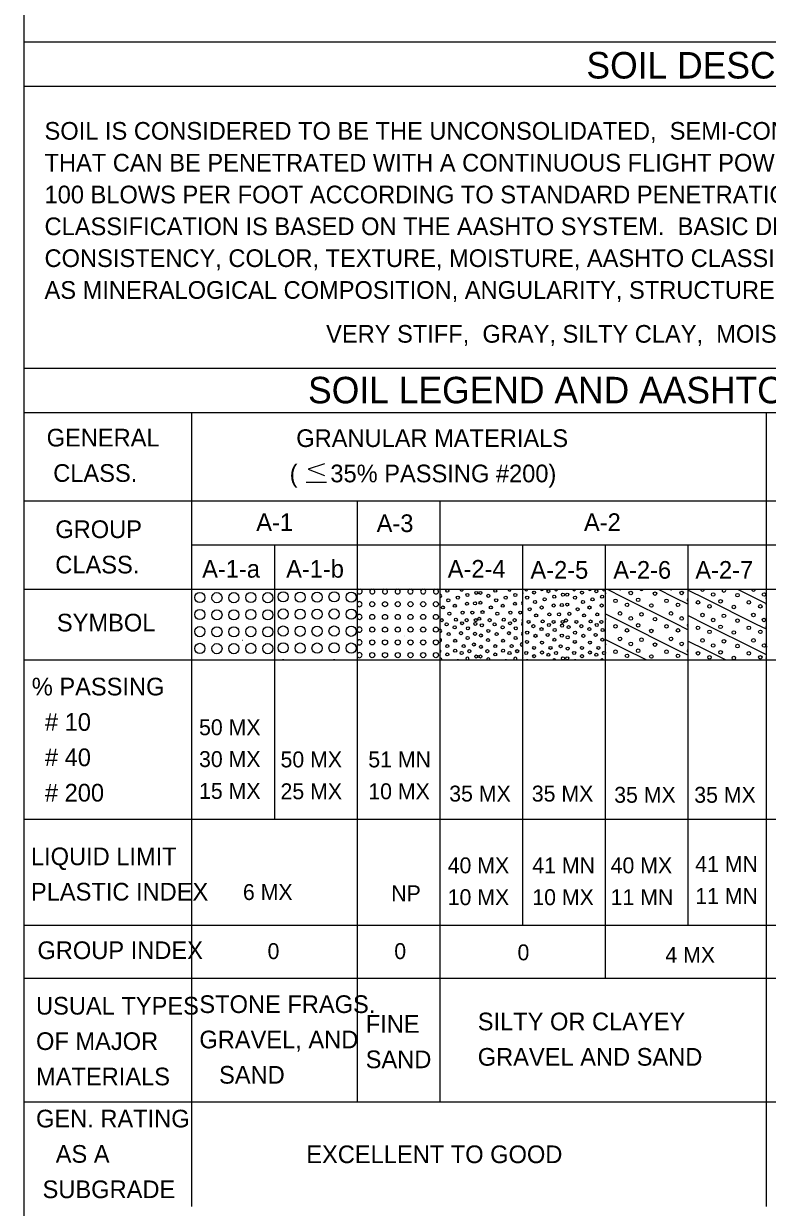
# Model space of a CAD drawing. Extents: x 278710 to 279187, y 171464 to 171625.
# Drawn here: x 279005.33 to 279023.58, y 171537.43 to 171566.47 of the extents above; entities that cross this region are included whole.
import ezdxf

# ---------------------------------------------------------------- set-up
doc = ezdxf.new("R2010")
doc.units = 0
doc.layers.add('Geotech Sheets and Borders Cell', color=7, linetype='Continuous')

msp = doc.modelspace()

# ---------------------------------------------------------------- linework, layer by layer
at = {"layer": 'Geotech Sheets and Borders Cell'}
for p, q in [((279005.33, 171581.203), (279005.33, 171485.806)), ((279005.33, 171566.02), (279158.027, 171566.02)), ((279005.33, 171564.936), (279158.027, 171564.936)), ((279005.33, 171558.017), (279043.07, 171558.017)), ((279005.33, 171556.932), (279043.07, 171556.932)), ((279009.451, 171556.932), (279009.451, 171537.446)), ((279023.549, 171556.932), (279023.549, 171537.446)), ((279012.262, 171555.223), (279012.761, 171555.223)), ((279005.33, 171554.763), (279043.07, 171554.763)), ((279013.52, 171540.014), (279013.52, 171554.754)), ((279015.55, 171540.014), (279015.55, 171554.754)), ((279009.451, 171553.679), (279031.791, 171553.679)), ((279011.49, 171546.955), (279011.49, 171553.683)), ((279017.58, 171544.352), (279017.58, 171553.683)), ((279019.61, 171543.051), (279019.61, 171553.683)), ((279021.641, 171544.352), (279021.641, 171553.683)), ((279005.33, 171552.594), (279043.07, 171552.594)), ((279010.696, 171552.593), (279010.696, 171552.594)), ((279010.696, 171552.593), (279010.697, 171552.593)), ((279019.648, 171552.594), (279020.036, 171552.4)), ((279020.036, 171552.4), (279021.286, 171551.775)), ((279020.898, 171552.594), (279021.286, 171552.4)), ((279021.286, 171552.4), (279021.641, 171552.223)), ((279021.641, 171552.572), (279022.058, 171552.363)), ((279022.058, 171552.363), (279023.308, 171551.738)), ((279022.846, 171552.594), (279023.308, 171552.363)), ((279023.308, 171552.363), (279023.549, 171552.243)), ((279019.61, 171551.988), (279020.036, 171551.775)), ((279020.036, 171551.775), (279021.286, 171551.15)), ((279021.286, 171551.775), (279021.641, 171551.598)), ((279021.641, 171551.947), (279022.058, 171551.738)), ((279022.058, 171551.738), (279023.308, 171551.113)), ((279023.308, 171551.738), (279023.549, 171551.618)), ((279010.696, 171551.343), (279010.696, 171551.344)), ((279010.696, 171551.343), (279010.697, 171551.343)), ((279011.49, 171551.357), (279011.49, 171551.357)), ((279012.739, 171551.358), (279012.739, 171551.358)), ((279012.739, 171551.358), (279012.74, 171551.357)), ((279014.666, 171551.446), (279014.667, 171551.446)), ((279014.666, 171551.445), (279014.666, 171551.445)), ((279014.666, 171551.445), (279014.667, 171551.444)), ((279019.61, 171551.363), (279020.036, 171551.15)), ((279021.641, 171551.322), (279022.058, 171551.113)), ((279020.036, 171551.15), (279020.618, 171550.859)), ((279021.286, 171551.15), (279021.641, 171550.973)), ((279022.058, 171551.113), (279022.566, 171550.859)), ((279023.308, 171551.113), (279023.549, 171550.993)), ((279005.33, 171550.859), (279043.07, 171550.859)), ((279005.33, 171546.955), (279043.07, 171546.955)), ((279005.33, 171544.352), (279031.791, 171544.352)), ((279005.33, 171543.051), (279031.791, 171543.051)), ((279005.33, 171540.014), (279043.07, 171540.014))]:
    msp.add_line(p, q, dxfattribs=at)
msp.add_lwpolyline([(279012.709, 171555.665), (279012.314, 171555.535), (279012.709, 171555.379)], dxfattribs=at)
for centre, radius in [((279009.655, 171552.391), 0.125), ((279010.074, 171552.385), 0.125), ((279010.487, 171552.385), 0.125), ((279010.905, 171552.391), 0.125), ((279011.324, 171552.385), 0.125), ((279011.698, 171552.405), 0.125), ((279012.117, 171552.399), 0.125), ((279012.53, 171552.399), 0.125), ((279012.948, 171552.405), 0.125), ((279013.367, 171552.399), 0.125), ((279015.727, 171552.555), 0.0375), ((279015.751, 171552.322), 0.0375), ((279015.986, 171552.386), 0.0375), ((279016.221, 171552.452), 0.0375), ((279016.436, 171552.503), 0.0375), ((279016.54, 171552.503), 0.0375), ((279016.733, 171552.43), 0.0375), ((279016.903, 171552.555), 0.0375), ((279016.926, 171552.322), 0.0375), ((279017.161, 171552.386), 0.0375), ((279017.396, 171552.452), 0.0375), ((279017.687, 171552.386), 0.0375), ((279017.857, 171552.511), 0.0375), ((279018.116, 171552.343), 0.0375), ((279018.209, 171552.545), 0.0375), ((279018.351, 171552.409), 0.0375), ((279018.566, 171552.46), 0.0375), ((279018.67, 171552.46), 0.0375), ((279018.862, 171552.386), 0.0375), ((279019.032, 171552.511), 0.0375), ((279019.291, 171552.343), 0.0375), ((279019.384, 171552.545), 0.0375), ((279019.526, 171552.409), 0.0375), ((279019.856, 171552.308), 0.0438), ((279020.229, 171552.501), 0.0438), ((279020.41, 171552.333), 0.0438), ((279020.825, 171552.484), 0.0438), ((279021.106, 171552.308), 0.0438), ((279021.479, 171552.501), 0.0438), ((279022.251, 171552.463), 0.0438), ((279022.433, 171552.296), 0.0438), ((279022.848, 171552.447), 0.0438), ((279023.501, 171552.463), 0.0438), ((279009.655, 171551.971), 0.125), ((279010.074, 171551.966), 0.125), ((279010.487, 171551.966), 0.125), ((279010.905, 171551.971), 0.125), ((279011.324, 171551.966), 0.125), ((279011.698, 171551.985), 0.125), ((279012.117, 171551.98), 0.125), ((279012.53, 171551.98), 0.125), ((279012.948, 171551.985), 0.125), ((279013.367, 171551.98), 0.125), ((279013.885, 171552.226), 0.0625), ((279014.198, 171552.226), 0.0625), ((279014.51, 171552.226), 0.0625), ((279014.823, 171552.226), 0.0625), ((279015.135, 171552.226), 0.0625), ((279015.448, 171552.226), 0.0625), ((279015.619, 171552.146), 0.0375), ((279015.912, 171552.187), 0.0375), ((279016.101, 171552.018), 0.0375), ((279016.209, 171552.236), 0.0375), ((279016.34, 171552.021), 0.0375), ((279016.408, 171552.248), 0.0375), ((279016.54, 171552.26), 0.0375), ((279016.591, 171552.032), 0.0375), ((279016.795, 171552.146), 0.0375), ((279017.088, 171552.187), 0.0375), ((279017.277, 171552.018), 0.0375), ((279017.385, 171552.236), 0.0375), ((279017.516, 171552.021), 0.0375), ((279017.749, 171552.102), 0.0375), ((279017.881, 171552.279), 0.0375), ((279018.042, 171552.144), 0.0375), ((279018.339, 171552.193), 0.0375), ((279018.538, 171552.205), 0.0375), ((279018.67, 171552.216), 0.0375), ((279018.925, 171552.102), 0.0375), ((279019.056, 171552.279), 0.0375), ((279019.217, 171552.144), 0.0375), ((279019.515, 171552.193), 0.0375), ((279019.967, 171551.999), 0.0438), ((279020.138, 171552.209), 0.0438), ((279020.736, 171552.193), 0.0438), ((279021.217, 171551.999), 0.0438), ((279021.388, 171552.209), 0.0438), ((279021.878, 171552.271), 0.0438), ((279022.161, 171552.172), 0.0438), ((279022.758, 171552.156), 0.0438), ((279023.128, 171552.271), 0.0438), ((279023.411, 171552.172), 0.0438), ((279013.885, 171551.914), 0.0625), ((279014.198, 171551.914), 0.0625), ((279014.51, 171551.914), 0.0625), ((279014.823, 171551.914), 0.0625), ((279015.135, 171551.914), 0.0625), ((279015.448, 171551.914), 0.0625), ((279015.591, 171551.834), 0.0375), ((279015.71, 171551.731), 0.0375), ((279015.778, 171551.993), 0.0375), ((279015.937, 171551.845), 0.0375), ((279016.09, 171551.759), 0.0375), ((279016.204, 171551.834), 0.0375), ((279016.414, 171551.742), 0.0375), ((279016.425, 171551.834), 0.0375), ((279016.511, 171551.868), 0.0375), ((279016.574, 171551.707), 0.0375), ((279016.766, 171551.834), 0.0375), ((279016.886, 171551.731), 0.0375), ((279016.954, 171551.993), 0.0375), ((279017.113, 171551.845), 0.0375), ((279017.266, 171551.759), 0.0375), ((279017.379, 171551.834), 0.0375), ((279017.721, 171551.791), 0.0375), ((279017.908, 171551.949), 0.0375), ((279018.067, 171551.802), 0.0375), ((279018.22, 171551.716), 0.0375), ((279018.231, 171551.974), 0.0375), ((279018.334, 171551.791), 0.0375), ((279018.47, 171551.978), 0.0375), ((279018.555, 171551.791), 0.0375), ((279018.641, 171551.825), 0.0375), ((279018.721, 171551.989), 0.0375), ((279018.896, 171551.791), 0.0375), ((279019.084, 171551.949), 0.0375), ((279019.242, 171551.802), 0.0375), ((279019.396, 171551.716), 0.0375), ((279019.407, 171551.974), 0.0375), ((279019.509, 171551.791), 0.0375), ((279020.229, 171551.876), 0.0438), ((279020.41, 171551.708), 0.0438), ((279020.492, 171551.978), 0.0438), ((279020.825, 171551.859), 0.0438), ((279021.479, 171551.876), 0.0438), ((279021.99, 171551.962), 0.0438), ((279022.251, 171551.838), 0.0438), ((279022.515, 171551.941), 0.0438), ((279022.848, 171551.822), 0.0438), ((279023.24, 171551.962), 0.0438), ((279023.501, 171551.838), 0.0438), ((279009.655, 171551.552), 0.125), ((279010.074, 171551.547), 0.125), ((279010.487, 171551.547), 0.125), ((279010.905, 171551.552), 0.125), ((279011.324, 171551.547), 0.125), ((279011.698, 171551.567), 0.125), ((279012.117, 171551.562), 0.125), ((279012.53, 171551.562), 0.125), ((279012.948, 171551.567), 0.125), ((279013.367, 171551.562), 0.125), ((279013.885, 171551.601), 0.0625), ((279014.198, 171551.601), 0.0625), ((279014.51, 171551.601), 0.0625), ((279014.823, 171551.601), 0.0625), ((279015.135, 171551.601), 0.0625), ((279015.448, 171551.601), 0.0625), ((279015.761, 171551.492), 0.0375), ((279015.909, 171551.657), 0.0375), ((279016.062, 171551.515), 0.0375), ((279016.232, 171551.634), 0.0375), ((279016.408, 171551.498), 0.0375), ((279016.551, 171551.458), 0.0375), ((279016.733, 171551.571), 0.0375), ((279016.937, 171551.492), 0.0375), ((279017.084, 171551.657), 0.0375), ((279017.238, 171551.515), 0.0375), ((279017.408, 171551.634), 0.0375), ((279017.687, 171551.527), 0.0375), ((279017.84, 171551.687), 0.0375), ((279017.891, 171551.449), 0.0375), ((279018.039, 171551.614), 0.0375), ((279018.192, 171551.472), 0.0375), ((279018.362, 171551.591), 0.0375), ((279018.538, 171551.455), 0.0375), ((279018.544, 171551.699), 0.0375), ((279018.704, 171551.664), 0.0375), ((279018.862, 171551.527), 0.0375), ((279019.016, 171551.687), 0.0375), ((279019.067, 171551.449), 0.0375), ((279019.214, 171551.614), 0.0375), ((279019.367, 171551.472), 0.0375), ((279019.537, 171551.591), 0.0375), ((279019.856, 171551.683), 0.0438), ((279020.138, 171551.584), 0.0438), ((279020.736, 171551.568), 0.0438), ((279021.106, 171551.683), 0.0438), ((279021.388, 171551.584), 0.0438), ((279021.878, 171551.646), 0.0438), ((279022.161, 171551.547), 0.0438), ((279022.433, 171551.671), 0.0438), ((279022.758, 171551.531), 0.0438), ((279023.128, 171551.646), 0.0438), ((279023.411, 171551.547), 0.0438), ((279009.655, 171551.141), 0.125), ((279010.074, 171551.135), 0.125), ((279010.487, 171551.135), 0.125), ((279010.905, 171551.141), 0.125), ((279011.324, 171551.135), 0.125), ((279011.698, 171551.155), 0.125), ((279012.117, 171551.149), 0.125), ((279012.53, 171551.149), 0.125), ((279012.948, 171551.155), 0.125), ((279013.367, 171551.149), 0.125), ((279013.885, 171551.289), 0.0625), ((279014.198, 171551.289), 0.0625), ((279014.51, 171551.289), 0.0625), ((279014.823, 171551.289), 0.0625), ((279015.135, 171551.289), 0.0625), ((279015.448, 171551.289), 0.0625), ((279015.727, 171551.197), 0.0375), ((279015.92, 171551.328), 0.0375), ((279016.13, 171551.197), 0.0375), ((279016.226, 171551.396), 0.0375), ((279016.379, 171551.237), 0.0375), ((279016.551, 171551.18), 0.0375), ((279016.727, 171551.345), 0.0375), ((279016.903, 171551.197), 0.0375), ((279017.096, 171551.328), 0.0375), ((279017.306, 171551.197), 0.0375), ((279017.402, 171551.396), 0.0375), ((279017.681, 171551.301), 0.0375), ((279017.857, 171551.154), 0.0375), ((279018.05, 171551.284), 0.0375), ((279018.26, 171551.154), 0.0375), ((279018.356, 171551.352), 0.0375), ((279018.509, 171551.194), 0.0375), ((279018.681, 171551.414), 0.0375), ((279018.681, 171551.137), 0.0375), ((279018.857, 171551.301), 0.0375), ((279019.032, 171551.154), 0.0375), ((279019.226, 171551.284), 0.0375), ((279019.436, 171551.154), 0.0375), ((279019.532, 171551.352), 0.0375), ((279019.967, 171551.374), 0.0438), ((279020.229, 171551.251), 0.0438), ((279020.492, 171551.353), 0.0438), ((279020.825, 171551.234), 0.0438), ((279021.217, 171551.374), 0.0438), ((279021.479, 171551.251), 0.0438), ((279021.99, 171551.337), 0.0438), ((279022.251, 171551.213), 0.0438), ((279022.515, 171551.316), 0.0438), ((279022.848, 171551.197), 0.0438), ((279023.24, 171551.337), 0.0438), ((279023.501, 171551.213), 0.0438), ((279013.885, 171550.976), 0.0625), ((279014.198, 171550.976), 0.0625), ((279014.51, 171550.976), 0.0625), ((279014.823, 171550.976), 0.0625), ((279015.135, 171550.976), 0.0625), ((279015.448, 171550.976), 0.0625), ((279015.727, 171550.993), 0.0375), ((279015.92, 171551.084), 0.0375), ((279016.079, 171551.027), 0.0375), ((279016.266, 171551.073), 0.0375), ((279016.436, 171550.942), 0.0375), ((279016.54, 171550.942), 0.0375), ((279016.71, 171551.073), 0.0375), ((279016.903, 171550.993), 0.0375), ((279017.096, 171551.084), 0.0375), ((279017.254, 171551.027), 0.0375), ((279017.442, 171551.073), 0.0375), ((279017.664, 171551.029), 0.0375), ((279017.857, 171550.95), 0.0375), ((279018.05, 171551.041), 0.0375), ((279018.209, 171550.984), 0.0375), ((279018.396, 171551.029), 0.0375), ((279018.566, 171550.899), 0.0375), ((279018.67, 171550.899), 0.0375), ((279018.84, 171551.029), 0.0375), ((279019.032, 171550.95), 0.0375), ((279019.226, 171551.041), 0.0375), ((279019.384, 171550.984), 0.0375), ((279019.572, 171551.029), 0.0375), ((279019.856, 171551.058), 0.0438), ((279020.138, 171550.959), 0.0438), ((279020.41, 171551.083), 0.0438), ((279020.736, 171550.943), 0.0438), ((279021.106, 171551.058), 0.0438), ((279021.388, 171550.959), 0.0438), ((279021.878, 171551.021), 0.0438), ((279022.161, 171550.922), 0.0438), ((279022.433, 171551.046), 0.0438), ((279022.758, 171550.906), 0.0438), ((279023.128, 171551.021), 0.0438), ((279023.411, 171550.922), 0.0438)]:
    msp.add_circle(centre, radius, dxfattribs=at)
for centre, radius, start, end in [((279013.573, 171552.539), 0.0625, 117.2937, 147.8104), ((279013.573, 171552.539), 0.0625, 212.1896, 62.7063), ((279013.885, 171552.539), 0.0625, 117.2937, 62.7063), ((279014.198, 171552.539), 0.0625, 117.2937, 62.7063), ((279014.51, 171552.539), 0.0625, 117.2937, 62.7063), ((279014.823, 171552.539), 0.0625, 117.2937, 62.7063), ((279015.135, 171552.539), 0.0625, 117.2937, 62.7063), ((279015.448, 171552.539), 0.0625, 117.2937, 62.7063), ((279015.557, 171552.43), 0.0375, 259.1391, 100.8609), ((279016.079, 171552.588), 0.0375, 171.147, 8.853), ((279017.254, 171552.588), 0.0375, 171.147, 8.853), ((279017.612, 171552.503), 0.0375, 148.7579, 211.2421), ((279017.664, 171552.591), 0.0375, 174.4692, 5.5308), ((279018.05, 171552.602), 0.0375, 191.7487, 348.2513), ((279018.396, 171552.591), 0.0375, 174.4692, 5.5308), ((279018.84, 171552.591), 0.0375, 174.4692, 5.5308), ((279019.226, 171552.602), 0.0375, 191.7487, 348.2513), ((279019.572, 171552.591), 0.0375, 174.4692, 5.5308), ((279019.575, 171552.484), 0.0438, 322.3805, 37.6195), ((279019.967, 171552.624), 0.0438, 223.6373, 316.3627), ((279020.492, 171552.603), 0.0438, 191.793, 348.207), ((279021.217, 171552.624), 0.0438, 223.6373, 316.3627), ((279021.66, 171552.333), 0.0438, 116.2386, 243.7614), ((279021.598, 171552.447), 0.0438, 350.9144, 9.0856), ((279021.99, 171552.587), 0.0438, 170.7511, 9.2489), ((279022.515, 171552.566), 0.0438, 139.7264, 40.2736), ((279023.24, 171552.587), 0.0438, 170.7511, 9.2489), ((279023.539, 171552.374), 0.0125, 324.1084, 35.8916), ((279013.573, 171552.226), 0.0625, 212.1896, 147.8104), ((279017.584, 171552.248), 0.0375, 96.0262, 263.9738), ((279023.544, 171552.233), 0.0125, 291.108, 68.892), ((279013.573, 171551.914), 0.0625, 212.1896, 147.8104), ((279017.589, 171551.742), 0.0375, 104.7726, 255.2274), ((279017.601, 171551.834), 0.0375, 123.7096, 236.2904), ((279017.545, 171551.989), 0.0375, 338.4467, 21.5533), ((279019.646, 171551.978), 0.0375, 162.3921, 197.6079), ((279019.575, 171551.859), 0.0438, 322.3805, 37.6195), ((279021.66, 171551.708), 0.0438, 116.2386, 243.7614), ((279021.598, 171551.822), 0.0438, 350.9144, 9.0856), ((279013.573, 171551.601), 0.0625, 212.1896, 147.8104), ((279015.557, 171551.571), 0.0375, 259.1391, 100.8609), ((279017.584, 171551.498), 0.0375, 96.0262, 263.9738), ((279023.544, 171551.666), 0.0125, 291.108, 68.892), ((279013.573, 171551.289), 0.0625, 212.1896, 147.8104), ((279015.551, 171551.345), 0.0375, 267.7979, 92.2021), ((279017.555, 171551.237), 0.0375, 48.5716, 311.4284), ((279019.575, 171551.234), 0.0438, 322.3805, 37.6195), ((279021.598, 171551.197), 0.0438, 350.9144, 9.0856), ((279023.556, 171551.187), 0.0125, 237.325, 122.675), ((279013.573, 171550.976), 0.0625, 212.1896, 147.8104), ((279015.534, 171551.073), 0.0375, 294.3038, 65.6962), ((279015.557, 171550.868), 0.0375, 345.7476, 100.8609), ((279016.221, 171550.891), 0.0375, 302.2, 237.8), ((279016.733, 171550.868), 0.0375, 345.7476, 194.2524), ((279017.396, 171550.891), 0.0375, 302.2, 237.8), ((279017.612, 171550.942), 0.0375, 148.7579, 211.2421), ((279018.351, 171550.847), 0.0375, 18.2374, 161.7626), ((279019.526, 171550.847), 0.0375, 18.2374, 161.7626), ((279021.66, 171551.083), 0.0438, 116.2386, 243.7614), ((279023.539, 171550.903), 0.0125, 324.1084, 35.8916), ((279011.698, 171550.735), 0.125, 82.1331, 97.8669), ((279012.948, 171550.735), 0.125, 82.1331, 97.8669), ((279015.986, 171550.825), 0.0375, 64.663, 115.337), ((279017.161, 171550.825), 0.0375, 64.663, 115.337), ((279017.687, 171550.825), 0.0375, 65.917, 114.083), ((279018.862, 171550.825), 0.0375, 65.917, 114.083)]:
    msp.add_arc(centre, radius, start, end, dxfattribs=at)

# ---------------------------------------------------------------- texts
for s, height, p in [('SOIL DESCRIPTION', 0.6507, (279019.142, 171565.122)), ('SOIL IS CONSIDERED TO BE THE UNCONSOLIDATED,  SEMI-CONSOLIDATED, OR WEATHERED EARTH MATERIALS ', 0.43381, (279005.842, 171563.621)), ('THAT CAN BE PENETRATED WITH A CONTINUOUS FLIGHT POWER AUGER, AND YIELD LESS THAN ', 0.43381, (279005.842, 171562.84)), ('100 BLOWS PER FOOT ACCORDING TO STANDARD PENETRATION TEST (AASHTO T206, ASTM D-1586).  SOIL ', 0.43381, (279005.842, 171562.06)), ('CLASSIFICATION IS BASED ON THE AASHTO SYSTEM.  BASIC DESCRIPTIONS GENERALLY SHALL INCLUDE:', 0.43381, (279005.842, 171561.279)), ('CONSISTENCY, COLOR, TEXTURE, MOISTURE, AASHTO CLASSIFICATION, AND OTHER PERTINENT FACTORS SUCH ', 0.43381, (279005.842, 171560.498)), ('AS MINERALOGICAL COMPOSITION, ANGULARITY, STRUCTURE, PLASTICITY, ETC. EXAMPLE:', 0.43381, (279005.842, 171559.717)), ('VERY STIFF,  GRAY, SILTY CLAY,  MOIST WITH INTERBEDDED FINE SAND LAYERS, HIGHLY PLASTIC,  A-7-6', 0.43381, (279012.753, 171558.641)), ('SOIL LEGEND AND AASHTO CLASSIFICATION', 0.6507, (279012.31, 171557.153)), ('GENERAL', 0.4338, (279005.894, 171556.095)), (' GRANULAR MATERIALS', 0.43381, (279011.858, 171556.082)), (' CLASS.', 0.4338, (279005.894, 171555.227)), ('(     35% PASSING #200)', 0.43381, (279011.858, 171555.216)), ('A-1', 0.4338, (279011.038, 171554.021)), ('A-3', 0.4338, (279013.993, 171553.995)), ('A-2', 0.4338, (279019.081, 171554.021)), ('GROUP', 0.4338, (279006.106, 171553.848)), ('CLASS.', 0.4338, (279006.106, 171552.98)), ('A-1-a', 0.4338, (279009.711, 171552.876)), ('A-1-b', 0.4338, (279011.772, 171552.876)), ('A-2-4', 0.4338, (279015.737, 171552.876)), ('A-2-5', 0.4338, (279017.767, 171552.85)), ('A-2-6', 0.4338, (279019.801, 171552.85)), ('A-2-7', 0.4338, (279021.814, 171552.85)), ('SYMBOL', 0.4338, (279006.145, 171551.557)), ('% PASSING', 0.4338, (279005.529, 171549.987)), ('  # 10', 0.4338, (279005.529, 171549.119)), ('50 MX', 0.3904, (279009.634, 171549.011)), ('  # 40', 0.4338, (279005.529, 171548.252)), ('30 MX', 0.3904, (279009.634, 171548.23)), ('50 MX', 0.3904, (279011.634, 171548.222)), ('51 MN', 0.3904, (279013.788, 171548.222)), ('  # 200', 0.4338, (279005.529, 171547.384)), ('15 MX', 0.3904, (279009.634, 171547.449)), ('25 MX', 0.3904, (279011.634, 171547.44)), ('10 MX', 0.3904, (279013.788, 171547.44)), ('35 MX', 0.3904, (279015.775, 171547.384)), ('35 MX', 0.3904, (279017.801, 171547.384)), ('35 MX', 0.3904, (279019.823, 171547.354)), ('35 MX', 0.3904, (279021.788, 171547.354)), ('LIQUID LIMIT', 0.43381, (279005.508, 171545.822)), ('40 MX', 0.3904, (279015.737, 171545.623)), ('41 MN', 0.3904, (279017.813, 171545.623)), ('40 MX', 0.3904, (279019.736, 171545.623)), ('41 MN', 0.3904, (279021.812, 171545.654)), ('PLASTIC INDEX', 0.43381, (279005.508, 171544.955)), ('6 MX', 0.3904, (279010.711, 171544.968)), ('NP', 0.3904, (279014.351, 171544.938)), ('10 MX', 0.3904, (279015.737, 171544.842)), ('10 MX', 0.3904, (279017.813, 171544.842)), ('11 MN', 0.3904, (279019.736, 171544.842)), ('11 MN', 0.3904, (279021.812, 171544.872)), ('GROUP INDEX', 0.43381, (279005.668, 171543.519)), ('0', 0.39, (279011.316, 171543.519)), ('0', 0.39, (279014.426, 171543.519)), ('0', 0.39, (279017.45, 171543.489)), ('4 MX', 0.3904, (279021.079, 171543.428)), ('USUAL TYPES', 0.43381, (279005.633, 171542.157)), ('STONE FRAGS.', 0.43381, (279009.642, 171542.196)), ('SILTY OR CLAYEY', 0.43381, (279016.474, 171541.771)), ('FINE', 0.4338, (279013.724, 171541.71)), ('OF MAJOR', 0.4338, (279005.633, 171541.289)), ('GRAVEL, AND', 0.43381, (279009.642, 171541.329)), ('GRAVEL AND SAND', 0.43381, (279016.474, 171540.903)), ('SAND', 0.4338, (279013.724, 171540.842)), ('MATERIALS', 0.4338, (279005.633, 171540.422)), ('   SAND', 0.4338, (279009.642, 171540.463)), ('GEN. RATING', 0.43381, (279005.633, 171539.389)), ('   AS A', 0.4338, (279005.633, 171538.522)), ('EXCELLENT TO GOOD', 0.43381, (279012.266, 171538.513)), (' SUBGRADE', 0.4338, (279005.633, 171537.654))]:
    msp.add_text(s, height=height, dxfattribs=at).set_placement(p)

doc.saveas('drawing.dxf')
